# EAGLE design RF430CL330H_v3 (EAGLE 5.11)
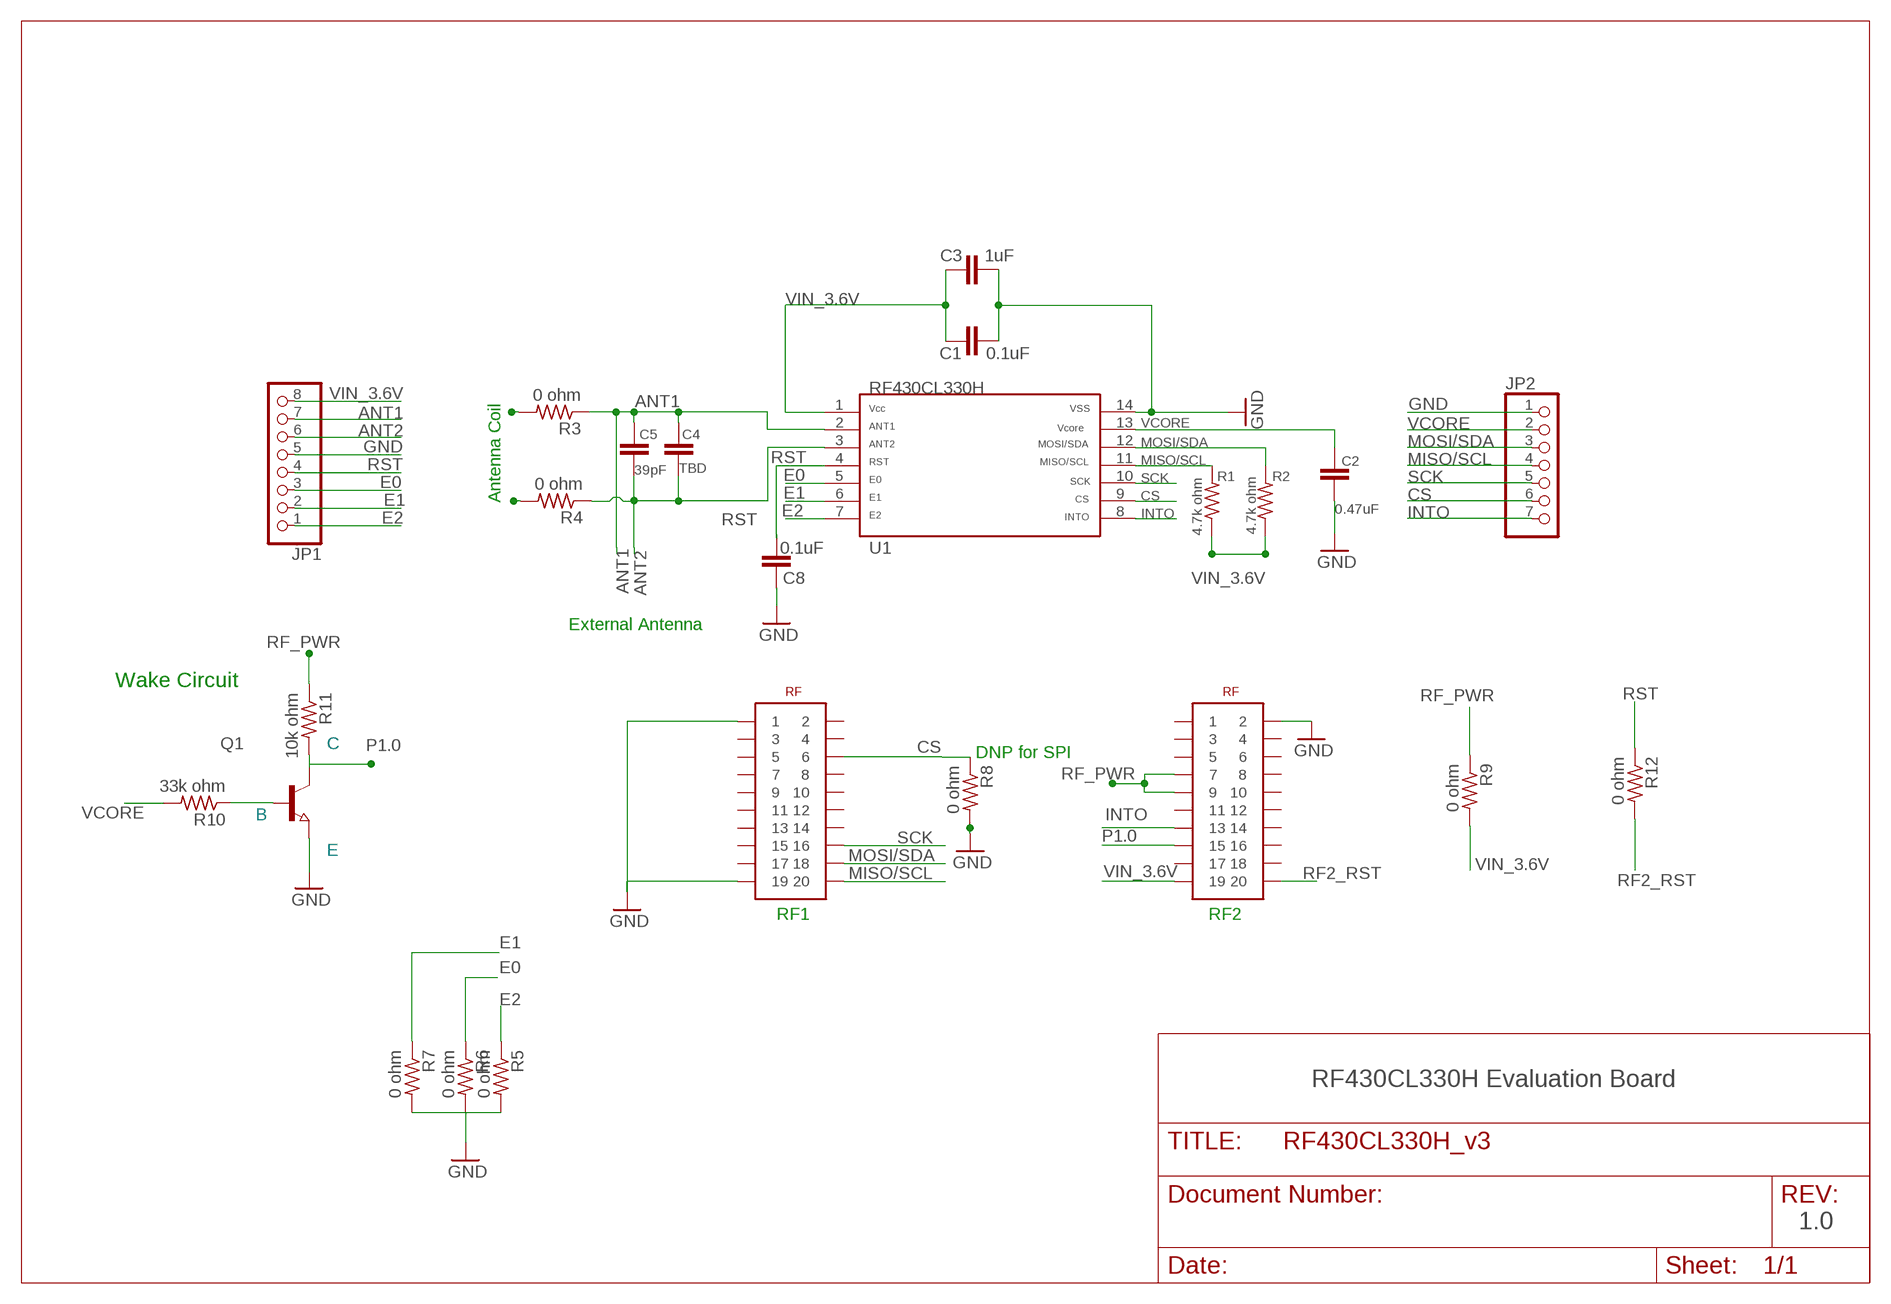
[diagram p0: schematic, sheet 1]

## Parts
C1  0.1uF  C-EUC0603  [C0603]
C2  0.47uF  C-EUC0603  [C0603]
C3  1uF  C-EUC0603  [C0603]
C4  TBD  C-EUC0603  [C0603]
C5  39pF  C-EUC0603  [C0603]
C8  0.1uF  C-EUC0603  [C0603]
JP1  PINHD-1X8  [1X08]
JP2  PINHD-1X7  [1X07]
Q1  NPN-TRANSISTOR_SOT23  [SOT23]
R1  4.7k ohm  R-US_R0402  [R0402]
R2  4.7k ohm  R-US_R0402  [R0402]
R3  0 ohm  R-US_R0402  [R0402]
R4  0 ohm  R-US_R0402  [R0402]
R5  0 ohm  R-US_R0402  [R0402]
R6  0 ohm  R-US_R0402  [R0402]
R7  0 ohm  R-US_R0402  [R0402]
R8  0 ohm  R-US_R0402  [R0402]
R9  0 ohm  R-US_R0402  [R0402]
R10  33k ohm  R-US_R0402  [R0402]
R11  10k ohm  R-US_R0402  [R0402]
R12  0 ohm  R-US_R0402  [R0402]
RF_HEADER  EM_HEADER  [TFM-110-02-SM-D-A-K]
U1  RF430CL330H  [PW14]

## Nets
ANT1: C4.1 C5.1 JP1.7 R3.1 U1.2
ANT2: C4.2 C5.2 JP1.6 R4.1 U1.3
CS: JP2.6 R8.1 RF_HEADER.6 U1.9
E0: JP1.3 R6.1 U1.5
E1: JP1.2 R7.1 U1.6
E2: JP1.1 R5.1 U1.7
GND [Ground]: C1.2 C2.2 C3.2 C8.1 JP1.5 JP2.1 Q1.2(E) R5.2 R6.2 R7.2 R8.2 RF_HEADER.1 RF_HEADER.19 RF_HEADER.22 U1.14
INTO: JP2.7 RF_HEADER.33 U1.8
MISO/SCL: JP2.4 R1.2 RF_HEADER.20 U1.11
MOSI/SDA: JP2.3 R2.2 RF_HEADER.18 U1.12
N$1: Q1.1(B) R10.1
N$3: R4.2
N$9: R3.2
P1.0: Q1.3(C) R11.2 RF_HEADER.35
RF2_RST: R12.2 RF_HEADER.40
RF_PWR: R9.1 R11.1 RF_HEADER.27 RF_HEADER.29
RST: C8.2 JP1.4 R12.1 U1.4
SCK: JP2.5 RF_HEADER.16 U1.10
VCORE: C2.1 JP2.2 R10.2 U1.13
VIN_3.6V: C1.1 C3.1 JP1.8 R1.1 R2.1 R9.2 RF_HEADER.39 U1.1
Unconnected: RF_HEADER.2 RF_HEADER.3 RF_HEADER.4 RF_HEADER.5 RF_HEADER.7 RF_HEADER.8 RF_HEADER.9 RF_HEADER.10 RF_HEADER.11 RF_HEADER.12 RF_HEADER.13 RF_HEADER.14 RF_HEADER.15 RF_HEADER.17 RF_HEADER.21 RF_HEADER.23 RF_HEADER.24 RF_HEADER.25 RF_HEADER.26 RF_HEADER.28 RF_HEADER.30 RF_HEADER.31 RF_HEADER.32 RF_HEADER.34 RF_HEADER.36 RF_HEADER.37 RF_HEADER.38

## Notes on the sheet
- Antenna Coil
- External Antenna
- Wake Circuit
- DNP for SPI
- RF1 | RF2
- RF430CL330H Evaluation Board
- 1.0

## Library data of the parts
C1-C5 C8 = resistor:C-EU: CAPACITOR, European symbol
JP1 = pinhead:PINHD-1X8: PIN HEADER
JP2 = pinhead:PINHD-1X7: PIN HEADER
Q1 = RFID_Automotive:NPN-TRANSISTOR_: NPN TRANSISTOR
R1-R12 = rcl:R-US_: RESISTOR, American symbol
RF_HEADER = _MSP430_RF:EM_HEADER
U1 = TI_MSP430_v16:RF430CL330H: RF430CL330H ISO14443B Dynamic NFC Tag

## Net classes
0 Default: width 0.254 mm, drill 0.305 mm, clearance 0.152 mm
1 Ground: width 0.305 mm, drill 0.305 mm, clearance 0.152 mm to class 0, clearance 0.152 mm
2 Power: width 0.406 mm, drill 0.305 mm, clearance 0.152 mm to class 0, clearance 0.152 mm to class 1, clearance 0.152 mm

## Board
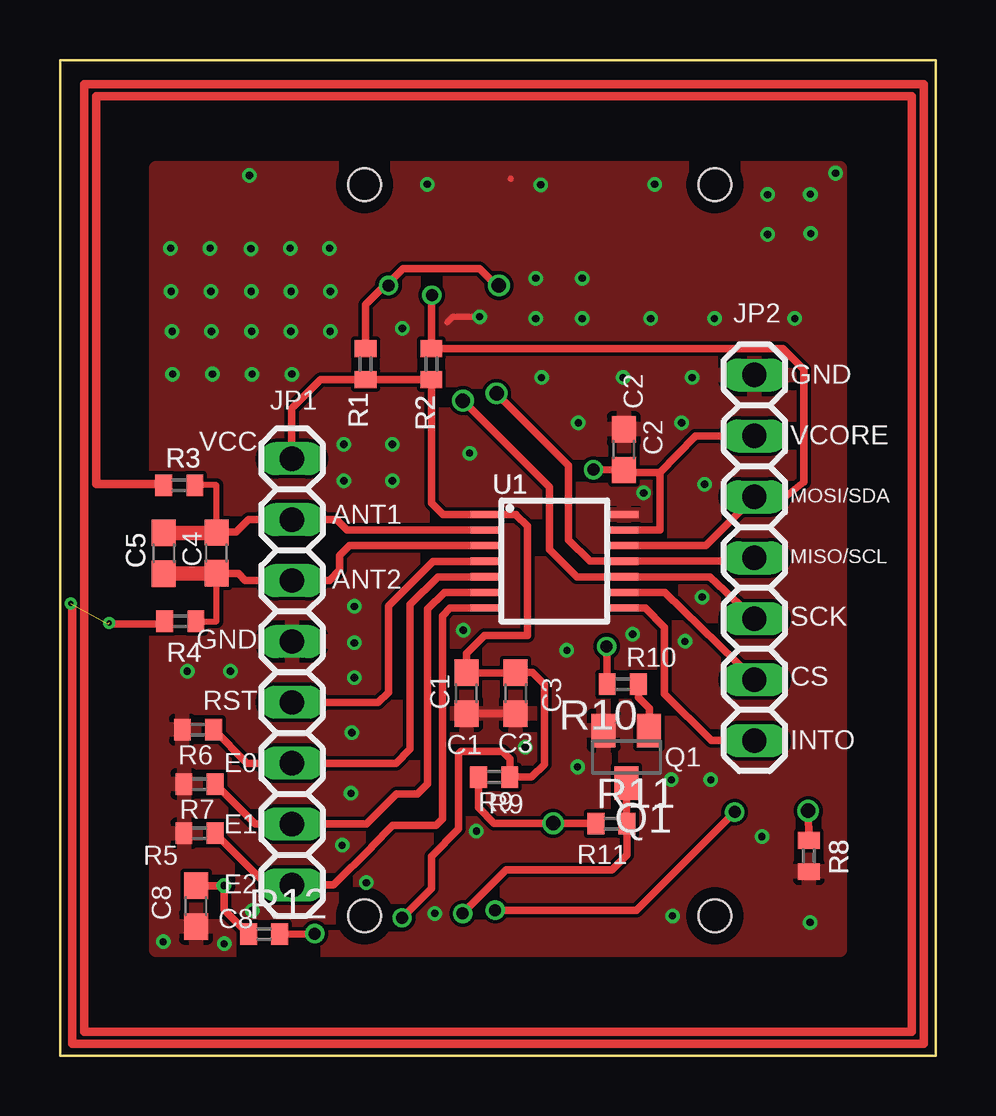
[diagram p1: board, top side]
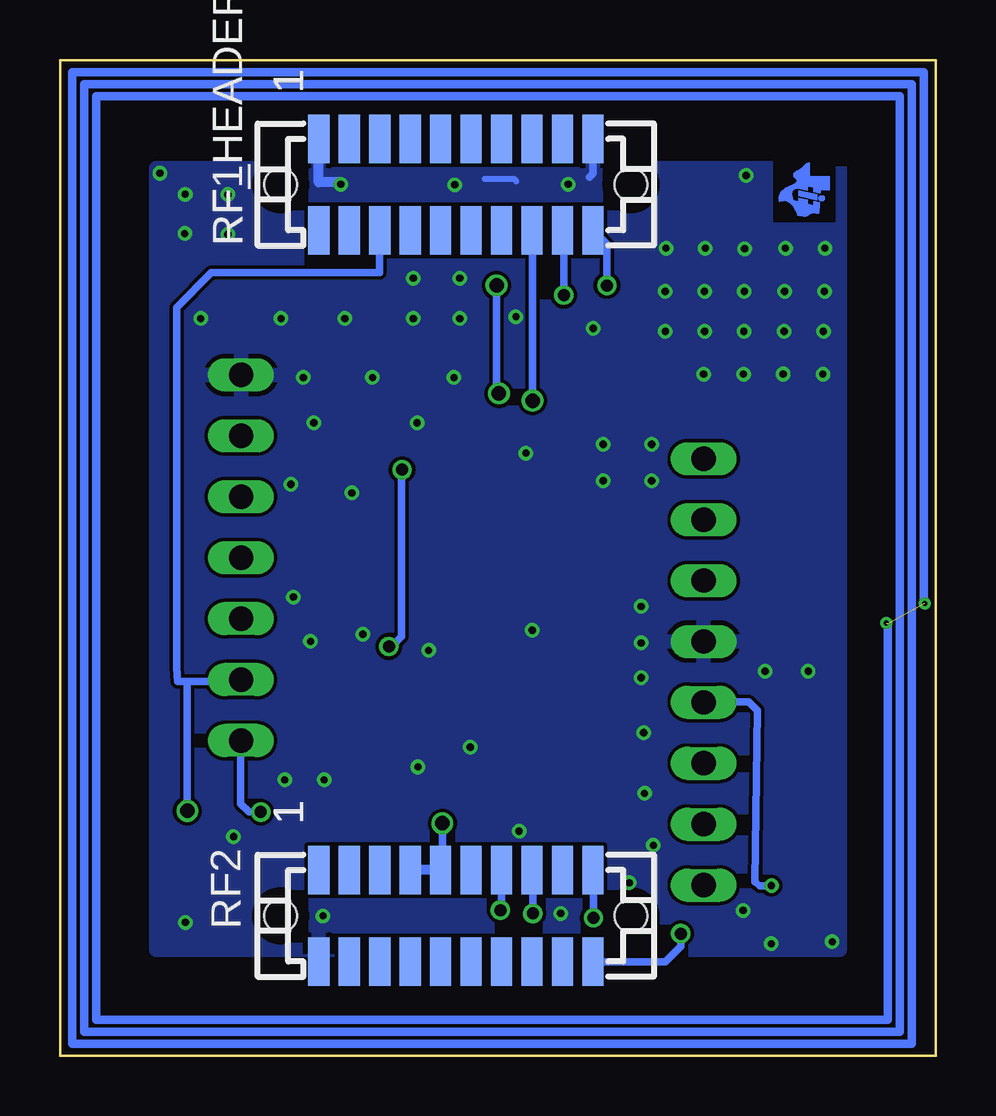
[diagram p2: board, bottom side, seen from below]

Size 36.5 x 41.5 mm. Coordinates in mm from the lower left corner, seen from the top.
Outline: 0,0 36.5,0 36.5,41.5 0,41.5 0,0
Copper layers (1+2*15+16): Top 0.0178mm / dielectric 0.3048mm / GND 0.0356mm / dielectric 0.6858mm / PWR 0.0356mm / dielectric 0.3048mm / Bottom 0.0178mm
Design rules "5529 Design Rules": minimum track width 6mil, minimum drill 12mil, track to track 6mil, track to pad 6mil, pad to pad 6mil, via to via 6mil, smd to smd 6mil, copper to edge 20mil, drill to drill 8mil, minimum pad ring 7mil, minimum via ring 6mil, stop-mask expansion 0mil, vias tented up to drill 25mil, thermal gap 8mil

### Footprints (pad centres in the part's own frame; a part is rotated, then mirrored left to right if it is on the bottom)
C0603 = smd 1.1 x 1: 1 -0.85,0; 2 0.85,0
1X08 = drill 1.016 long: 1 -8.89,0; 2 -6.35,0; 3 -3.81,0; 4 -1.27,0; 5 1.27,0; 6 3.81,0; 7 6.35,0; 8 8.89,0
1X07 = drill 1.016 long: 1 -7.62,0; 2 -5.08,0; 3 -2.54,0; 4 0,0; 5 2.54,0; 6 5.08,0; 7 7.62,0
SOT23 = smd 1 x 1.4: 1 -0.95,-1.1; 2 0.95,-1.1; 3 0,1.1
R0402 = smd 0.7 x 0.9: 1 -0.65,0; 2 0.65,0
TFM-110-02-SM-D-A-K = smd 2.032 x 0.889 bottom: 1 -1.905,5.715; 2 1.905,5.715; 3 -1.905,4.445; 4 1.905,4.445; 5 -1.905,3.175; 6 1.905,3.175; 7 -1.905,1.905; 8 1.905,1.905; 9 -1.905,0.635; 10 1.905,0.635; 11 -1.905,-0.635; 12 1.905,-0.635; 13 -1.905,-1.905; 14 1.905,-1.905; 15 -1.905,-3.175; 16 1.905,-3.175; 17 -1.905,-4.445; 18 1.905,-4.445; 19 -1.905,-5.715; 20 1.905,-5.715; 21 28.575,5.715; 22 32.385,5.715; 23 28.575,4.445; 24 32.385,4.445; 25 28.575,3.175; 26 32.385,3.175; 27 28.575,1.905; 28 32.385,1.905; 29 28.575,0.635; 30 32.385,0.635; 31 28.575,-0.635; 32 32.385,-0.635; 33 28.575,-1.905; 34 32.385,-1.905; 35 28.575,-3.175; 36 32.385,-3.175; 37 28.575,-4.445; 38 32.385,-4.445; 39 28.575,-5.715; 40 32.385,-5.715 | hole 1.359: 0,7.303; 0,-7.303; 30.48,7.303; 30.48,-7.303
PW14 = smd 0.3 x 1.2: 1 -1.95,-2.9; 2 -1.3,-2.9; 3 -0.65,-2.9; 4 0,-2.9; 5 0.65,-2.9; 6 1.3,-2.9; 7 1.95,-2.9; 8 1.95,2.9; 9 1.3,2.9; 10 0.65,2.9; 11 0,2.9; 12 -0.65,2.9; 13 -1.3,2.9; 14 -1.95,2.9

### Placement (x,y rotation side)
C1  16.94,15.1 270 top
C2  23.5,25.26 90 top
C3  19,15.1 270 top
C4  6.52,20.95 270 top
C5  4.33,20.94 270 top
C8  5.67,6.23 90 top
JP1  9.67,15.99 90 top
JP2  28.95,20.75 270 top
Q1  23.61,12.45 180 top
R1  12.74,28.82 90 top
R2  15.49,28.82 90 top
R3  4.97,23.77 180 top
R4  5.02,18.1 180 top
R5  5.82,9.27 180 top
R6  5.75,13.59 180 top
R7  5.82,11.32 180 top
R8  31.22,8.32 270 top
R9  18.1,11.61 0 top
R10  23.46,15.48 180 top
R11  22.99,9.67 0 top
R12  8.51,5.06 0 top
RF_HEADER  20,36.31 270 top
U1  20.61,20.61 270 top
U$4  [MSP430_LAB_TILOGO_SMALL]  5.21,36.01 270 bottom

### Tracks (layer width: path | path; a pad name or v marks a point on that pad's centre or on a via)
ANT1
  Top 0.254: R3.1 6.52,23.77 C4.1 6.54,21.82
  Top 0.305: U1.2 11.96,21.91 11.53,22.34 JP1.7 7.87,22.34 7.35,21.82 6.54,21.82
  Top 0.61: C5.1 C4.1
ANT2
  Top 0.254: R4.1 6.52,18.1 6.52,20.09 | JP1.6 | C4.2 6.53,20.09
  Top 0.305: U1.3 12.08,21.26 11.66,20.84 11.66,20.23 11.24,19.81 JP1.6 7.72,19.81 7.44,20.09 6.53,20.09
  Top 0.61: C5.2 6.52,20.09 C4.2
CS  (via drill 0.6)
  Top 0.305: U1.9 25.21,19.31 JP2.6 | R8.1 v31.19,10.2
  Bottom 0.305: RF_HEADER.6 23.17,33.63 23.17,32.63 30.19,32.63 31.63,31.17 31.63,16.16 31.59,15.6 31.09,15.6 | 31.09,15.6 28.92,15.6 JP2.6 | v31.19,10.2 31.19,15.5 31.09,15.6
E0
  Top 0.254: JP1.3
  Top 0.305: U1.5 15.75,19.95 14.6,18.8 14.6,12.78 14,12.18 JP1.3 7.81,12.18 R6.1
E1
  Top 0.305: U1.6 16.03,19.31 15.33,18.61 15.33,11.32 14.91,10.9 14.03,10.9 12.78,9.65 JP1.2 | JP1.2 | JP1.2 8.13,9.65 R7.1
E2
  Top 0.305: U1.7 16.27,18.66 15.94,18.33 15.94,9.86 15.67,9.59 14.21,9.59 | 14.21,9.59 14.2,9.6 | 14.21,9.59 13.87,9.59 12.98,8.7 12.98,8.68 11.41,7.11 JP1.1 8.64,7.1 R5.1
GND  (via drill 0.3)
  Top 0.254: 18.78,36.56 18.79,36.55 | 17.47,30.81 16.39,30.81 16.15,30.57
  Top 0.305: C1.2 C3.2
  Bottom 0.254: 17.47,36.44 17.58,36.55 18.79,36.55
  Bottom 0.305: 14.28,37.88 RF_HEADER.19 | 14.28,37.88 14.06,37.66 | 14.28,37.88 14.28,36.76 14.43,36.61
  Bottom 0.406: RF_HEADER.1 25.71,36.4 24.79,36.4 v24.79,36.32
  other vias: 17.07,25.11 26.87,23.81 14.27,30.31 25.49,11.49 26.05,17.26 26.77,19.11 20.07,28.26 23.87,17.56 31.27,5.55 32.33,36.78 21.57,12.03 12.13,10.93 12.16,13.46 21.13,16.89 16.81,17.73 19.83,32.4 4.31,4.74 30.63,30.72 27.28,30.72 15.31,36.32 7.89,36.69 21.61,26.37 11.83,25.48 17.49,30.8 7.1,16.02 12.27,18.72 17.36,9.35 6.84,4.66 4.63,31.85 6.25,33.65 24.33,23.45 19.39,12.85 6.29,31.85 4.61,33.65 7.97,31.85 9.59,33.65 9.63,31.85 7.95,33.63 9.62,30.19 9.66,28.4 7.98,30.19 8,28.4 6.31,30.19 6.35,28.41 6.35,28.4 4.67,30.19 4.69,28.4 21.77,32.4 21.77,30.72 19.83,30.72 24.62,30.72 27.13,11.49 29.26,9.12 5.3,16.02 12.27,17.2 12.27,15.75 11.76,8.76 12.77,7.2 8.02,6.05 29.5,35.89 31.3,34.27 29.5,34.23 31.28,35.91 23.47,28.26 26.35,28.26 25.91,26.37 13.85,25.48 11.83,23.96 13.85,23.96 11.23,33.65 11.27,31.85 11.26,30.19 20.04,36.3 25.53,5.82 15.62,5.92
  pour Bottom: 4,37 32.5,37 32.5,4.4 4,4.4
  pour Top: 32.5,37 32.5,4.4 4,4.4 4,37
INTO  (via drill 0.5)
  Top 0.305: U1.8 24.4,18.65 25.2,17.85 25.2,15.08 27.15,13.13 JP2.7 | v18.14,6.06 24.04,6.06 25.15,7.17 v28.13,10.15
  Bottom 0.305: RF_HEADER.33 18.09,6.11 v18.14,6.06 | v28.13,10.15 28.62,10.15 28.97,10.5 28.97,13.11 JP2.7
MISO/SCL  (via drill 0.5, 0.6)
  Top 0.305: JP2.4 28.81,20.61 U1.11 22.09,20.61 21.2,21.5 21.2,24.6 v18.2,27.6 | v18.3,32.1 18.19,32.1 17.49,32.8 14.31,32.8 13.7,32.19 v13.7,32.1 13.53,32.1 12.74,31.31 R1.2
  Bottom 0.305: v13.7,32.1 13.7,33.82 RF_HEADER.20 | v18.2,27.6 18.3,27.6 v18.3,32.1
MOSI/SDA  (via drill 0.5)
  Top 0.305: U1.12 26.92,21.26 JP2.3 29.1,23.26 30.2,23.27 31,23.9 31,24.2 31,28.6 30.13,29.47 R2.2 15.49,31.69 v15.5,31.7
  Bottom 0.305: v15.5,31.7 15.5,34.35 RF_HEADER.18
N$1
  Top 0.305: R10.1 24.11,14.93 24.57,14.47 Q1.1
N$2
  Top 0.35: 1.5,39.97 1.5,23.83 4.26,23.83 4.26,23.85
N$7  (via drill 0.2)  (3 unrouted)
  Top 0.305: 2,18 4.2,18
  Bottom 0.25: 2.1,1.5 2,1.5 2.1,1.5
  Bottom 0.35: 2.1,1.5 35,1.5 35,40 1.5,40 1.5,1 35.5,1 35.5,40.5 1,40.5 | 2,1.5 2,18
  other vias: 0.45,18.84 2.05,18.03
N$21  (1 unrouted)
  Top 0.35: 0.5,18.8 0.5,0.5 36,0.5 36,40.5 1,40.5
  Bottom 0.35: 1,40.5 1,0.5 36,0.5 36,41 0.5,41 0.5,18.8
N$22
  Top 0.35: 1,40.5 1,1 35.5,1 35.5,40 1.5,40
P1.0  (via drill 0.5)
  Top 0.305: Q1.3 23.61,9.7 R11.2 23.64,8.36 23.01,7.73 18.6,7.73 v16.79,5.92
  Bottom 0.305: v16.79,5.92 16.79,7.7 RF_HEADER.35
RF2_RST  (via drill 0.5)
  Top 0.305: v10.62,5.08 R12.2
  Bottom 0.305: v10.62,5.08 10.62,4.56 11.27,3.91 RF_HEADER.40
RF_PWR  (via drill 0.6)
  Top 0.305: R9.1 17.44,10.34 18.1,9.68 v20.56,9.68 R11.1
  Bottom 0.254: RF_HEADER.29 20.55,7.73 20.55,7.95
  Bottom 0.305: v20.56,9.68 20.55,7.95
  Bottom 0.406: RF_HEADER.29 RF_HEADER.27
RST  (via drill 0.3)
  Top 0.305: U1.4 17.7,20.6 15.55,20.6 13.69,18.74 13.69,15.14 13.27,14.72 JP1.4 | C8.2 v6.84,7.08 6.84,6.08 R12.1
  Bottom 0.305: JP1.4 7.78,14.73 7.43,14.38 7.53,7.24 7.33,7.08 v6.84,7.08
SCK  (via drill 0.6)
  Top 0.305: JP2.5 27.1,19.96 U1.10 21.54,19.96 20.4,21.1 20.4,23.7 v16.8,27.3
  Bottom 0.305: v16.8,27.3 16.8,34.38 RF_HEADER.16
VCORE  (via drill 0.5)
  Top 0.254: C2.1 23.61,24.41
  Top 0.305: 26.48,25.83 JP2.2 | 25,24.3 26.48,25.83 | 25,24.3 25,21.9 24.89,21.91 U1.13 | 26.48,25.83 26.5,25.8 | 25,24.3 23.5,24.3 C2.1 | R10.2 22.81,17.03 v22.79,17.05 | C2.1 23.49,24.42 | C2.1 23.08,24.41 v22.24,24.42
  Bottom 0.305: v22.79,17.05 22.67,17.05 22.26,17.46 22.26,24.39 v22.24,24.42
VIN_3.6V  (via drill 0.5)
  Top 0.254: JP1.8
  Top 0.305: JP1.8 9.66,26.97 10.86,28.17 R1.1 R2.1 15.49,23.04 15.97,22.56 U1.1 19.02,22.56 19.02,22.54 19.49,22.07 19.49,17.51 17.69,17.51 16.94,16.76 C1.1 C3.1 19.69,15.96 20.19,15.46 20.19,12.14 19.66,11.61 R9.2 18.75,12.37 18.44,12.68 16.71,12.68 16.61,12.58 16.61,9.44 15.48,8.31 15.48,6.96 v14.26,5.74
  Bottom 0.305: v14.26,5.74 14.26,7.71 RF_HEADER.39

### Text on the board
GND: G
PWR: P
_tplace: JP2 | JP1 | R1 | R1 | R1 | R1 | R2 | R2 | R2 | R2 | GND | VCC | R3 | R3 | R3 | C2 | VCORE | U1 | U1 | U1 | U1 | MOSI/SDA | C4 | ANT1 | MISO/SCL | C5 | C5 | ANT2 | GND | SCK | R10 | R4 | C1 | C3 | RST | CS | E0 | Q1 | INTO | R9 | E1 | R11 | R8 | R8 | R8 | E2 | C8
_bplace: 1 | 1 | 1 | 1 | RF1 | 1 | 1 | 1 | 1 | RF2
